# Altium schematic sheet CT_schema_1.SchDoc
size 672 x 485 mm
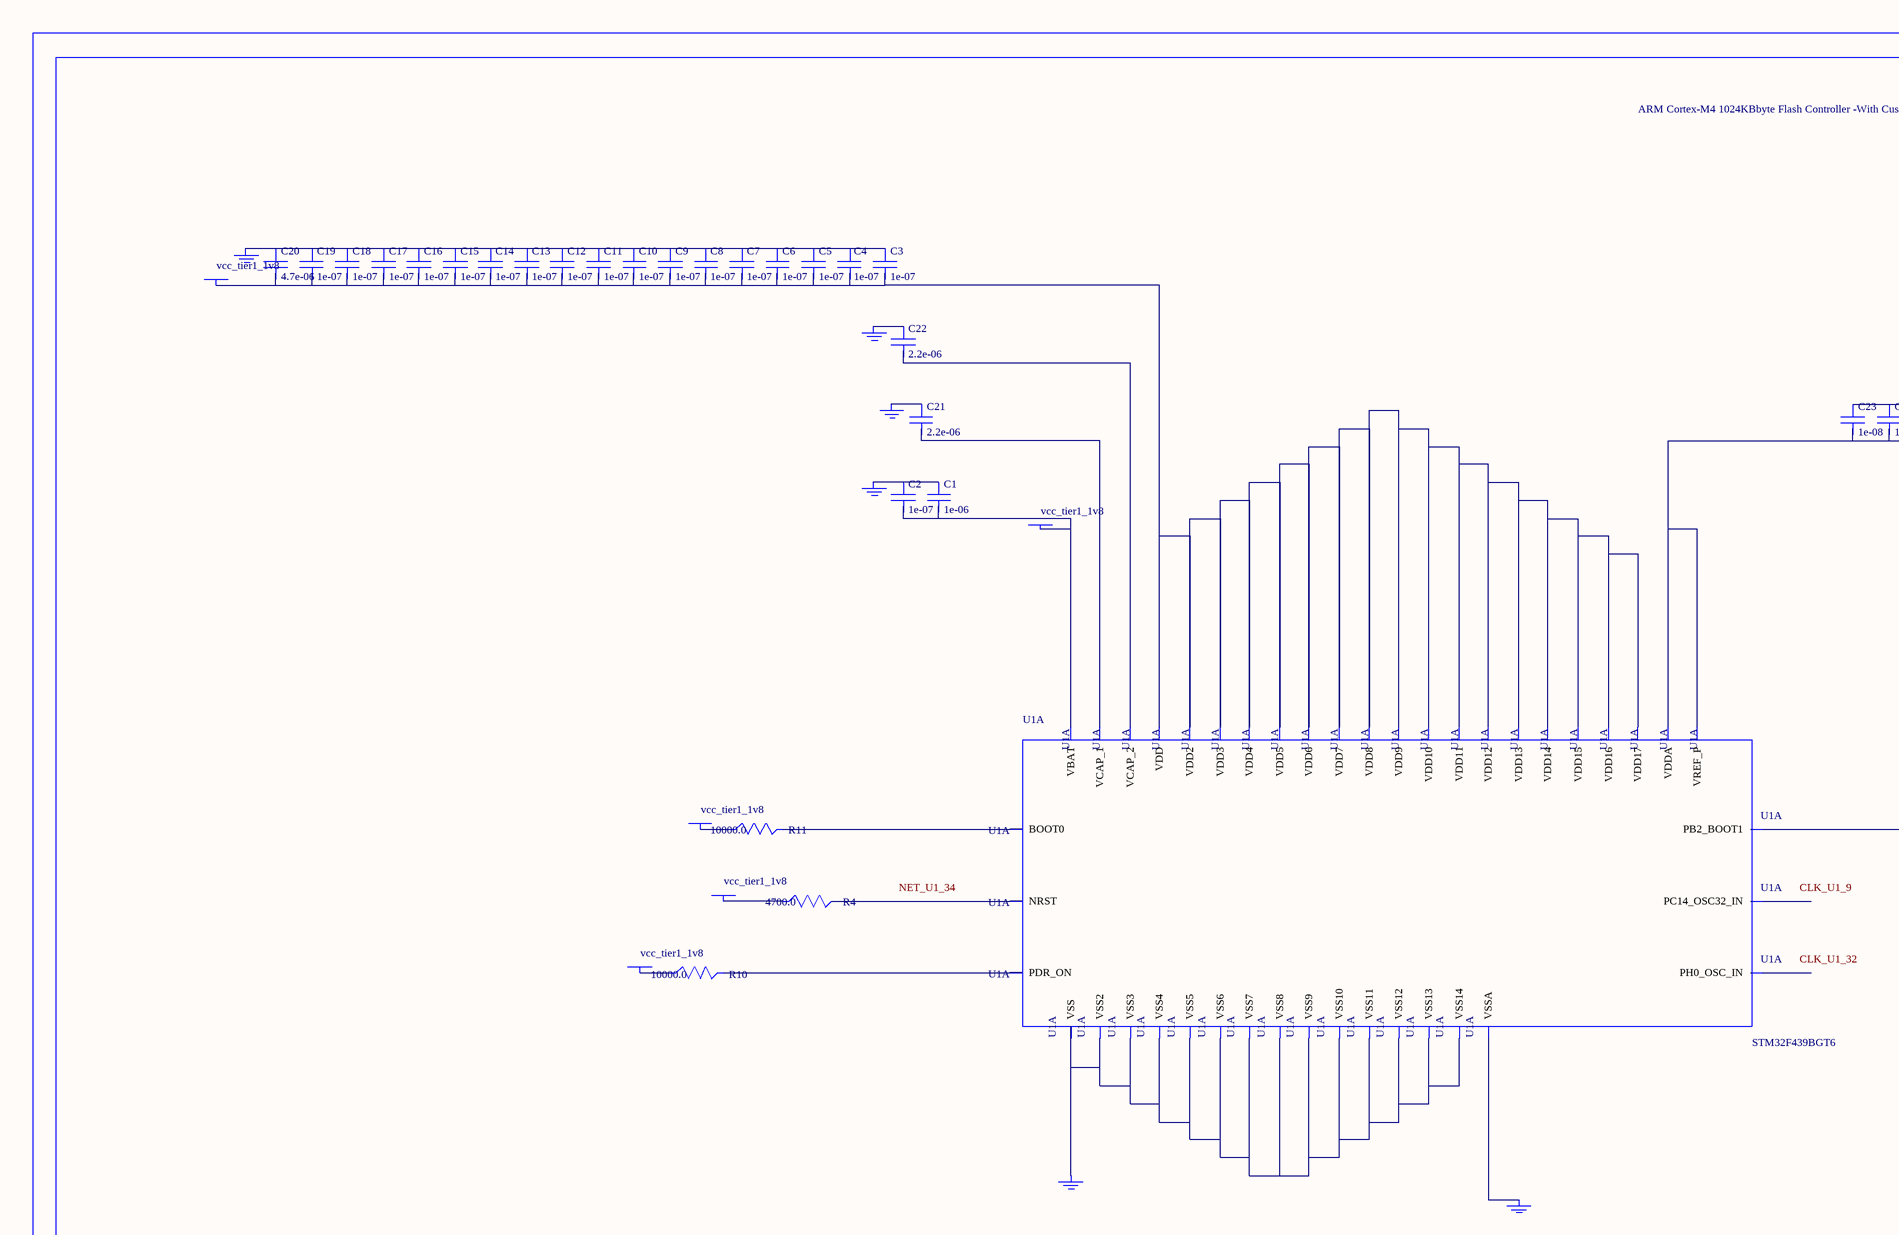
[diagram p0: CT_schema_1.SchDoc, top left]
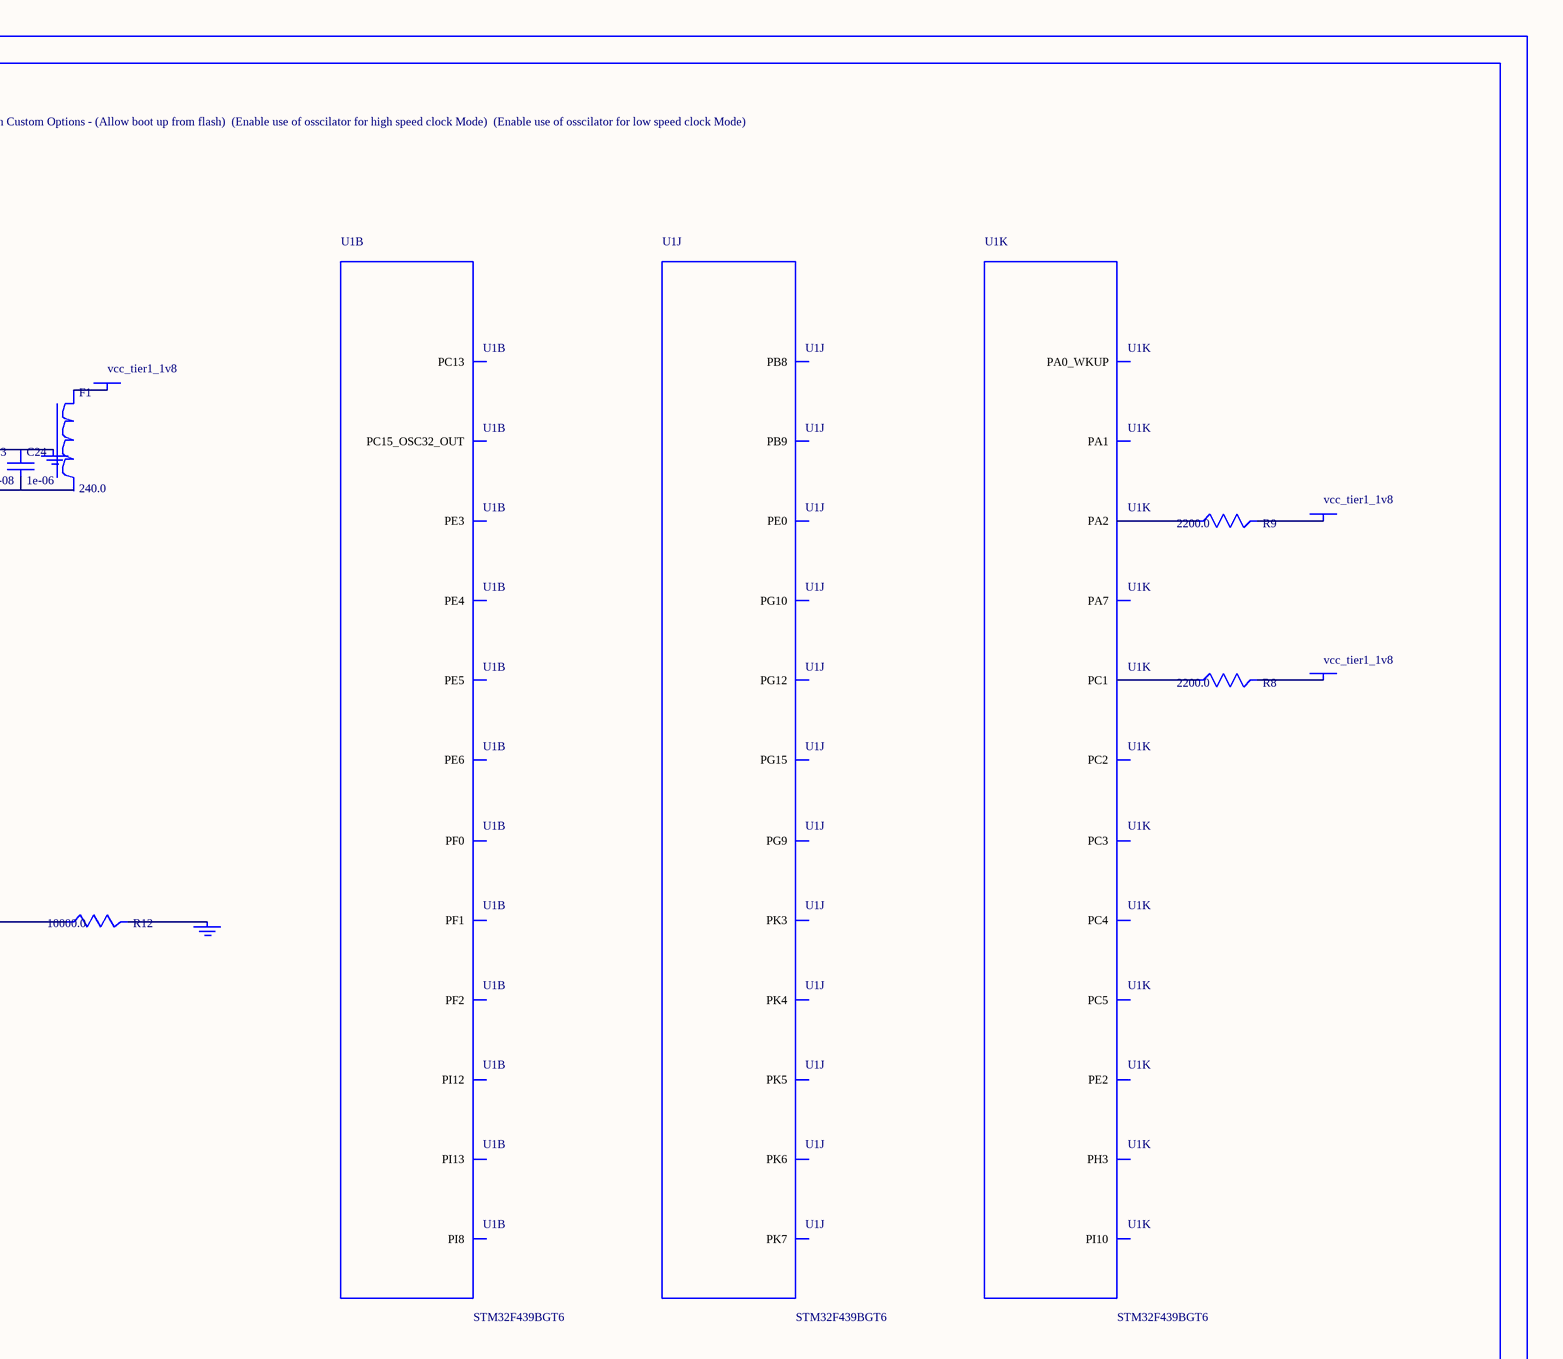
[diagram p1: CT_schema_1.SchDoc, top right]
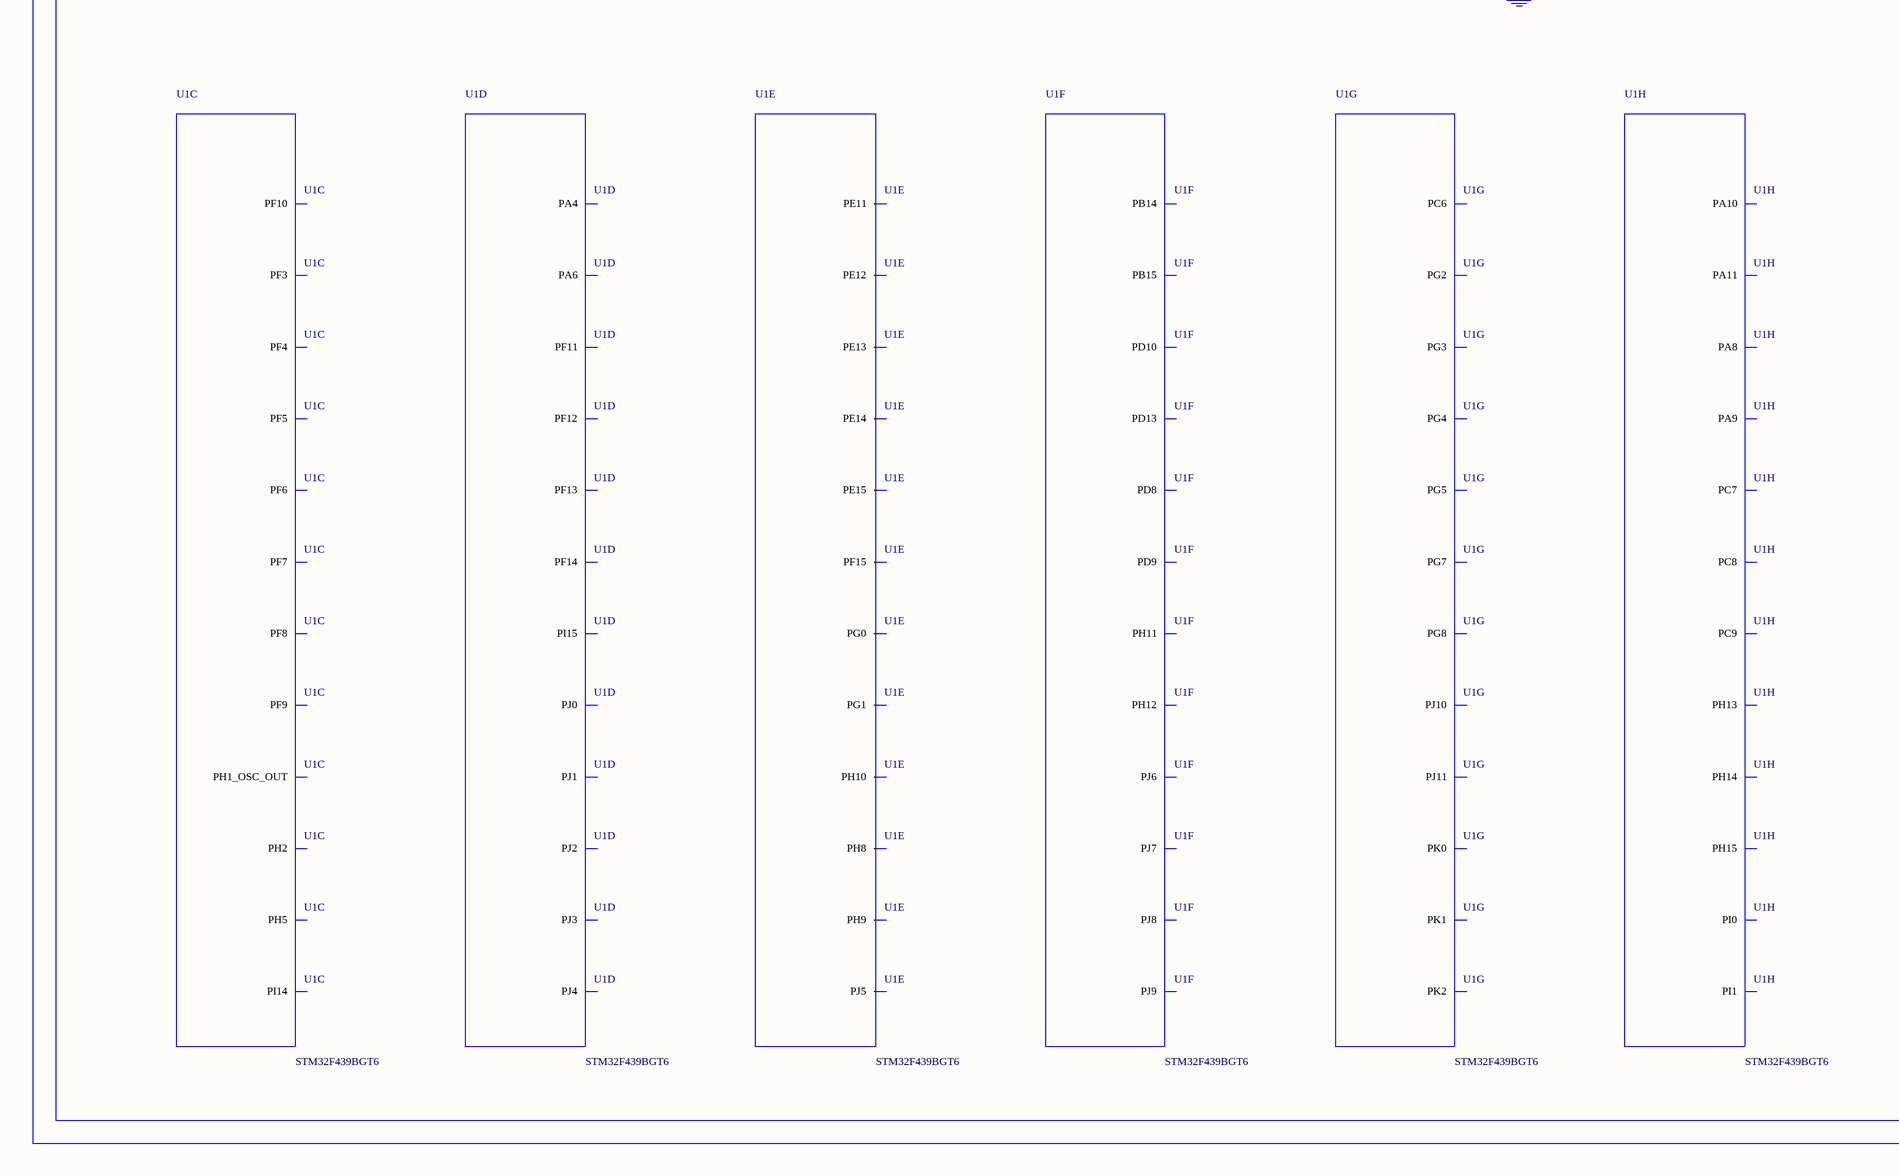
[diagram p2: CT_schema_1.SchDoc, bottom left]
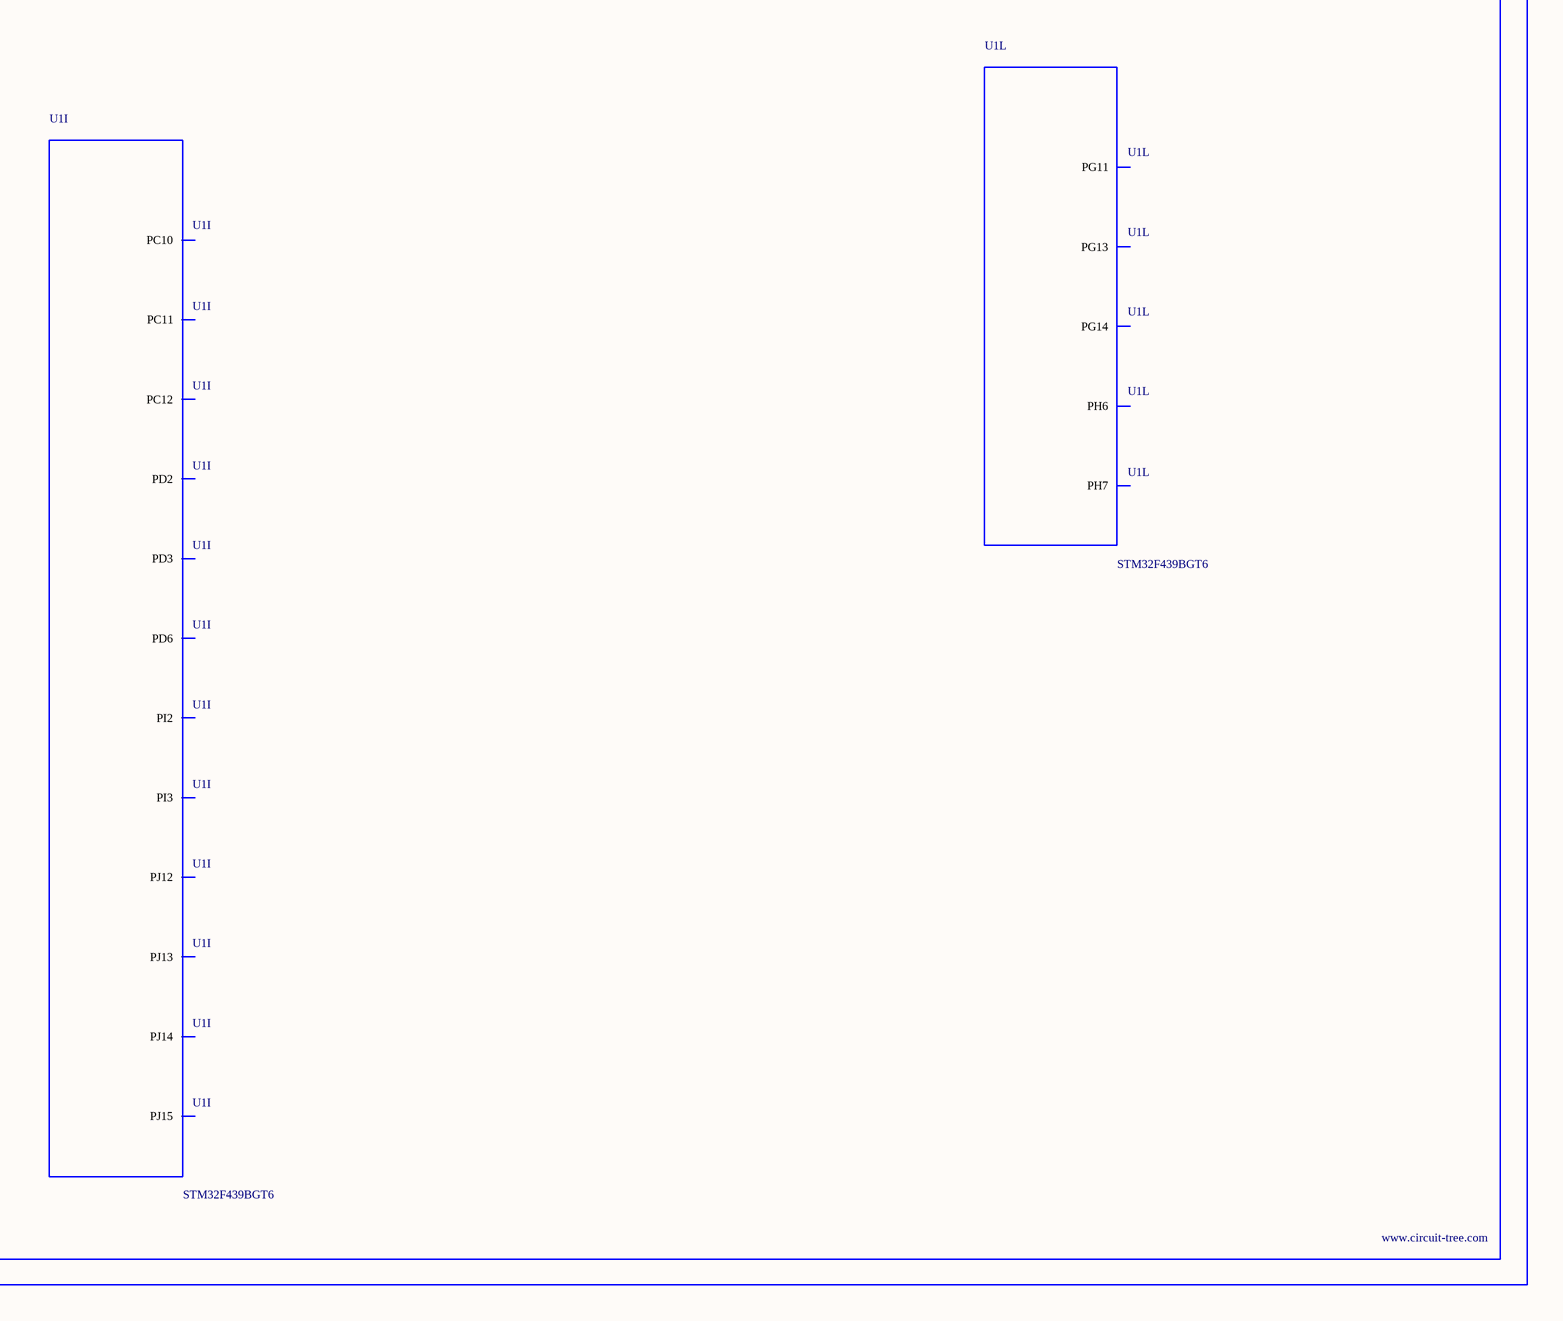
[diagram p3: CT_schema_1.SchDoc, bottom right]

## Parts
BORDER0  (no value)
C1  1e-06  [C0603]
C2  1e-07  [C0603]
C3  1e-07  [C0603]
C4  1e-07  [C0603]
C5  1e-07  [C0603]
C6  1e-07  [C0603]
C7  1e-07  [C0603]
C8  1e-07  [C0603]
C9  1e-07  [C0603]
C10  1e-07  [C0603]
C11  1e-07  [C0603]
C12  1e-07  [C0603]
C13  1e-07  [C0603]
C14  1e-07  [C0603]
C15  1e-07  [C0603]
C16  1e-07  [C0603]
C17  1e-07  [C0603]
C18  1e-07  [C0603]
C19  1e-07  [C0603]
C20  4.7e-06  [C0603]
C21  2.2e-06  [C0603]
C22  2.2e-06  [C0603]
C23  1e-08  [C0603]
C24  1e-06  [C0603]
F1  240.0  [L0603]
GND_INSTANCE_0_0  (no value)
GND_INSTANCE_0_1  (no value)
GND_INSTANCE_0_2  (no value)
GND_INSTANCE_0_3  (no value)
GND_INSTANCE_0_4  (no value)
GND_INSTANCE_0_5  (no value)
GND_INSTANCE_0_6  (no value)
GND_INSTANCE_0_7  (no value)
POWER_INSTANCE_0_0  vcc_tier1_1v8
POWER_INSTANCE_0_1  vcc_tier1_1v8
POWER_INSTANCE_0_2  vcc_tier1_1v8
POWER_INSTANCE_0_3  vcc_tier1_1v8
POWER_INSTANCE_0_4  vcc_tier1_1v8
POWER_INSTANCE_0_5  vcc_tier1_1v8
POWER_INSTANCE_0_6  vcc_tier1_1v8
POWER_INSTANCE_0_7  vcc_tier1_1v8
R4  4700.0  [R0603]
R8  2200.0  [R0603]
R9  2200.0  [R0603]
R10  10000.0  [R0603]
R11  10000.0  [R0603]
R12  10000.0  [R0603]
U1  STM32F439BGT6  [LQFP208]  (parts A,B,C,D,E,F,G,H,I,J,K,L of 18)

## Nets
NetC1_1: C1.1 C2.1 GND_INSTANCE_0_0.0(GND)
NetC1_2: C1.2 C2.2 POWER_INSTANCE_0_0.0(PWR) U1.6(VBAT)
NetC3_1: C3.1 C4.1 C5.1 C6.1 C7.1 C8.1 C9.1 C10.1 C11.1 C12.1 C13.1 C14.1 C15.1 C16.1 C17.1 C18.1 C19.1 C20.1 GND_INSTANCE_0_1.0(GND)
NetC3_2: C3.2 C4.2 C5.2 C6.2 C7.2 C8.2 C9.2 C10.2 C11.2 C12.2 C13.2 C14.2 C15.2 C16.2 C17.2 C18.2 C19.2 C20.2 POWER_INSTANCE_0_1.0(PWR) U1.15(VDD) U1.26(VDD2) U1.39(VDD3) U1.52(VDD4) U1.59(VDD5) U1.73(VDD6) U1.83(VDD7) U1.94(VDD8) U1.103(VDD9) U1.115(VDD10) U1.124(VDD11) U1.137(VDD12) U1.150(VDD13) U1.158(VDD14) U1.171(VDD15) U1.185(VDD16) U1.204(VDD17)
NetC21_1: C21.1 GND_INSTANCE_0_5.0(GND)
NetC21_2: C21.2 U1.92(VCAP_1)
NetC22_1: C22.1 GND_INSTANCE_0_6.0(GND)
NetC22_2: C22.2 U1.148(VCAP_2)
NetC23_1: C23.1 C24.1 GND_INSTANCE_0_3.0(GND)
NetC23_2: C23.2 C24.2 U1.41(VREF_P) U1.42(VDDA)
NetF1_1: F1.1 POWER_INSTANCE_0_2.0(PWR)
NetGND_INSTANCE_0_2_0: GND_INSTANCE_0_2.0(GND) U1.40(VSSA)
NetGND_INSTANCE_0_4_0: GND_INSTANCE_0_4.0(GND) R12.2
NetGND_INSTANCE_0_7_0: GND_INSTANCE_0_7.0(GND) U1.14(VSS) U1.25(VSS2) U1.51(VSS3) U1.60(VSS4) U1.72(VSS5) U1.82(VSS6) U1.93(VSS7) U1.114(VSS8) U1.125(VSS9) U1.136(VSS10) U1.149(VSS11) U1.170(VSS12) U1.184(VSS13) U1.202(VSS14)
NetPOWER_INSTANCE_0_3_0: POWER_INSTANCE_0_3.0(PWR) R11.1
NetPOWER_INSTANCE_0_4_0: POWER_INSTANCE_0_4.0(PWR) R10.1
NetPOWER_INSTANCE_0_5_0: POWER_INSTANCE_0_5.0(PWR) R4.1
NetPOWER_INSTANCE_0_6_0: POWER_INSTANCE_0_6.0(PWR) R8.2
NetPOWER_INSTANCE_0_7_0: POWER_INSTANCE_0_7.0(PWR) R9.2
NetR4_2: R4.2 U1.34(NRST)
NetR8_1: R8.1 U1.36(PC1)
NetR9_1: R9.1 U1.45(PA2)
NetR10_2: R10.2 U1.203(PDR_ON)
NetR11_2: R11.2 U1.197(BOOT0)
NetR12_1: R12.1 U1.63(PB2_BOOT1)

Not connected (* = marked no-connect by the designer): F1 2; U1 1(PE2) 2(PE3) 3(PE4) 4(PE5) 5(PE6) 7(PI8) 8(PC13) 9(PC14_OSC32_IN) 10(PC15_OSC32_OUT) 12(PI10) 16(PF0) 17(PF1) 18(PF2) 19(PI12) 20(PI13) 21(PI14) 22(PF3) 23(PF4) 24(PF5) 27(PF6) 28(PF7) 29(PF8) 30(PF9) 31(PF10) 32(PH0_OSC_IN) 33(PH1_OSC_OUT) 37(PC2) 38(PC3) 43(PA0_WKUP) 44(PA1) 46(PH2) 47(PH3) 49(PH5) 53(PA4) 55(PA6) 56(PA7) 57(PC4) 58(PC5) 64(PI15) 65(PJ0) 66(PJ1) 67(PJ2) 68(PJ3) 69(PJ4) 70(PF11) 71(PF12) 74(PF13) 75(PF14) 76(PF15) 77(PG0) 78(PG1) 85(PE11) 86(PE12) 87(PE13) 88(PE14) 89(PE15) 95(PJ5) 96(PH6) 97(PH7) 98(PH8) 99(PH9) 100(PH10) 101(PH11) 102(PH12) 106(PB14) 107(PB15) 108(PD8) 109(PD9) 110(PD10) 113(PD13) 118(PJ6) 119(PJ7) 120(PJ8) 121(PJ9) 122(PJ10) 123(PJ11) 126(PK0) 127(PK1) 128(PK2) 129(PG2) 130(PG3) 131(PG4) 132(PG5) 134(PG7) 135(PG8) 138(PC6) 139(PC7) 140(PC8) 141(PC9) 142(PA8) 143(PA9) 144(PA10) 145(PA11) 151(PH13) 152(PH14) 153(PH15) 154(PI0) 155(PI1) 156(PI2) 157(PI3) 161(PC10) 162(PC11) 163(PC12) 166(PD2) 167(PD3) 172(PD6) 174(PJ12) 175(PJ13) 176(PJ14) 177(PJ15) 178(PG9) 179(PG10) 180(PG11) 181(PG12) 182(PG13) 183(PG14) 186(PK3) 187(PK4) 188(PK5) 189(PK6) 190(PK7) 191(PG15) 198(PB8) 199(PB9) 200(PE0)

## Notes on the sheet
- Labels drawn without touching a wire or pin: CLK_U1_9, CLK_U1_32, NET_U1_34

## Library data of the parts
BORDER0 = BORDER_PAGE0
C1 C24 = C0603C105K3RACTU
C2-C19 = 06035C104K4Z2A
C20 = GRM188R6YA475KE15D
C21 C22 = C0603C225K8RACTU
C23 = 06035C103K4Z2A
F1 = Z0603C241ASMST
GND_INSTANCE_0_0-GND_INSTANCE_0_7 = GND
POWER_INSTANCE_0_0-POWER_INSTANCE_0_7 = PWR
R4 = RC0603JR-074K7L
R8 R9 = RC0603JR-072K2L
R10-R12 = RC0603JR-0710KL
